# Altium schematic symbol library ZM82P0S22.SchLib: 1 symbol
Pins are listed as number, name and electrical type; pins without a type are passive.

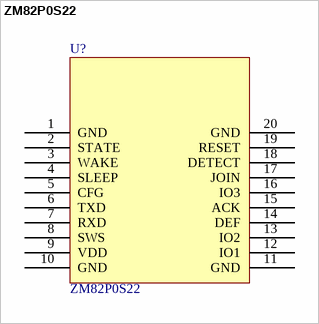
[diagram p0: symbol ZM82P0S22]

## ZM82P0S22
designator U?
-; 名称: PCB; PCB备注: 171116lmd; 器件优选方案: 正常状态，可以选用
footprint ZLG52810P0_Socket (Footprint not found)
pins: 1 GND, 2 STATE, 3 WAKE, 4 SLEEP, 5 CFG, 6 TXD, 7 RXD, 8 SWS, 9 VDD, 10 GND, 11 GND, 12 IO1, 13 IO2, 14 DEF, 15 ACK, 16 IO3, 17 JOIN, 18 DETECT, 19 RESET, 20 GND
